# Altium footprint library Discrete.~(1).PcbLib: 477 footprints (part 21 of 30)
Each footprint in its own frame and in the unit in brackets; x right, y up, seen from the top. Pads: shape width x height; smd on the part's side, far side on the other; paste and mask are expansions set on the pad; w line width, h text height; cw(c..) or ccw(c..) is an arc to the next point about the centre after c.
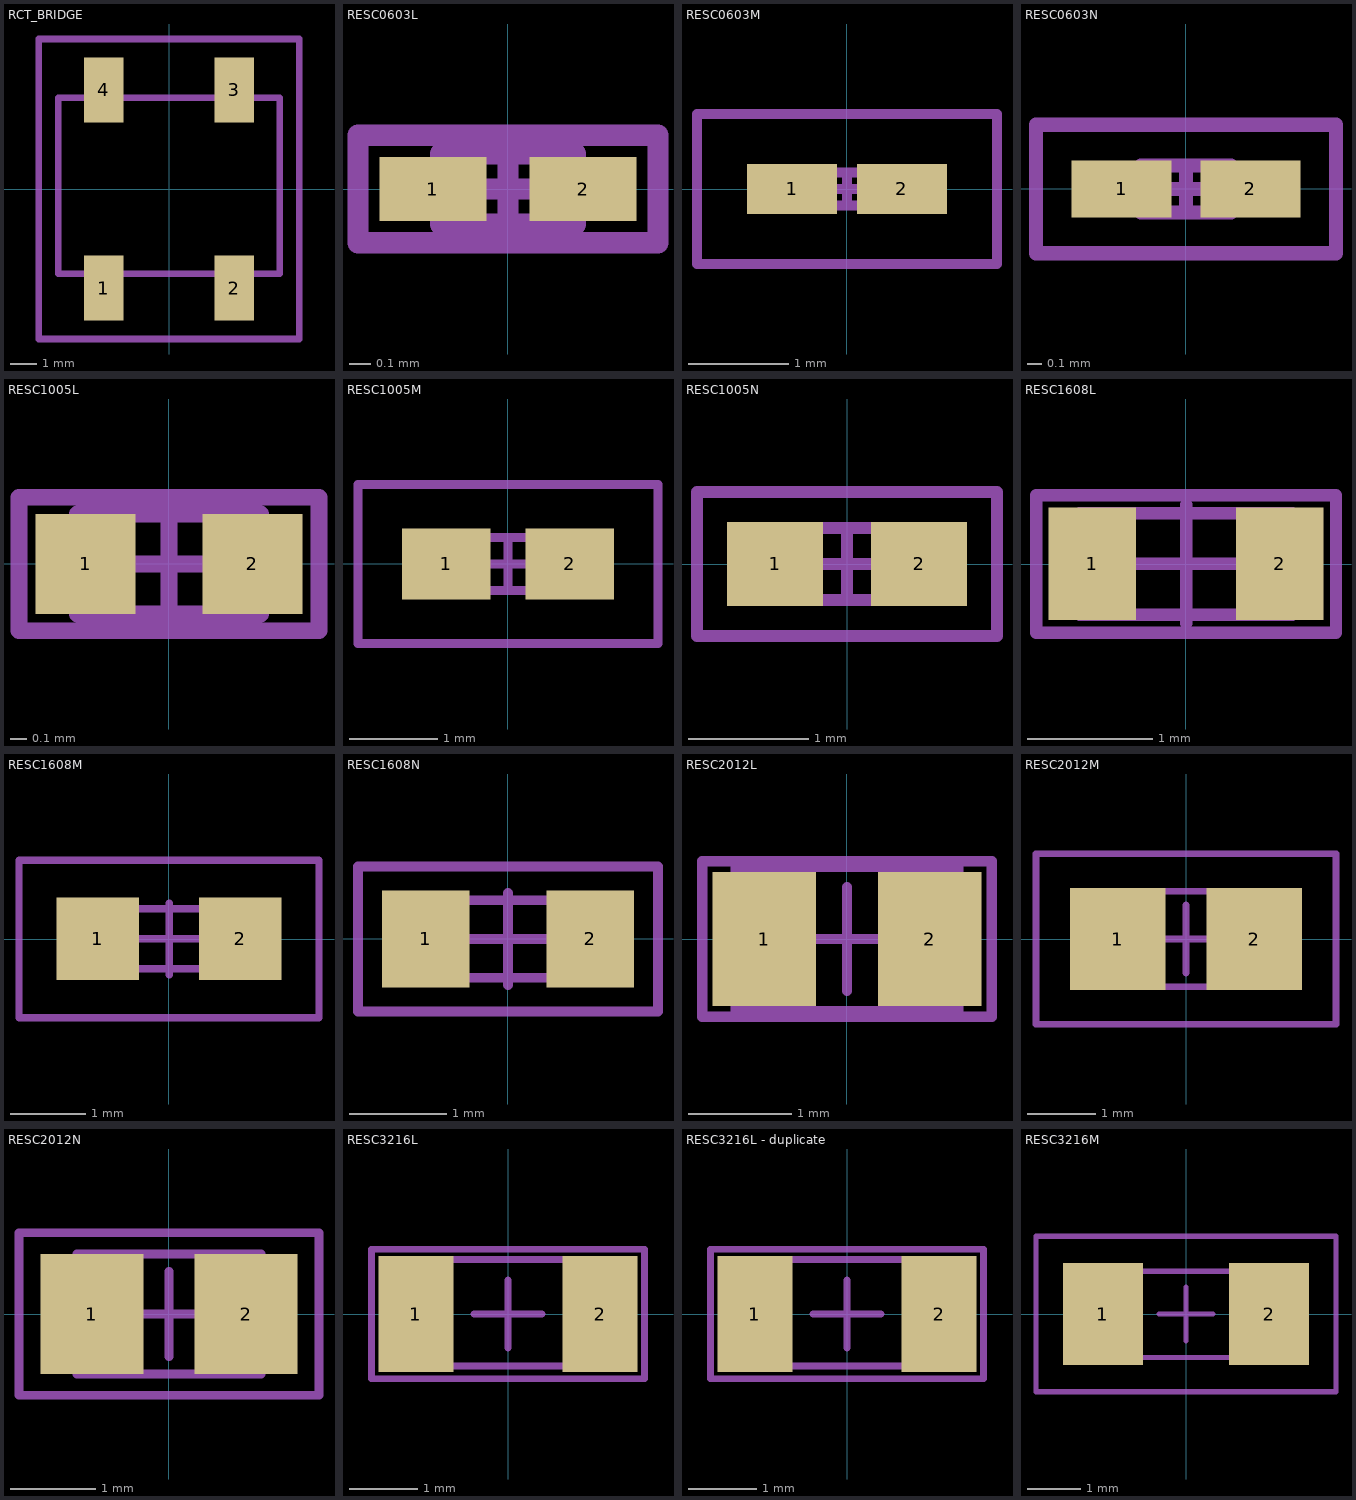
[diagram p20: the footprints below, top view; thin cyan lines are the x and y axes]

## RCT_BRIDGE [mm]
pads (4):
  rect 1.5x2.5 smd: 1(-2.5,-3.8) 2(2.5,-3.8) 3(2.5,3.8) 4(-2.5,3.8)
Mechanical 13:
  lines w0.254: -4.25,-3.25 -4.25,3.5 4.25,3.5 4.25,-3.25 -4.25,-3.25
Mechanical 15:
  lines w0.254: -5,-5.75 -5,5.75 5,5.75 5,-5.75 -5,-5.75
3D body: height 3, standoff 1, extent -4.25,-3.25 4.25,3.5

## RESC0603L [mm] "Chip Resistor, Body 0.6x0.3mm, IPC High Density"
height 0.3
pads (2):
  rect 0.5x0.3 smd: 1(-0.35,0) 2(0.35,0)
Mechanical 13:
  lines w0.1: -0.315,-0.165 0.315,-0.165 0.315,0.165 -0.315,0.165 -0.315,-0.165
Mechanical 15:
  lines w0.1: -0.165,0 0.165,0 ; 0,-0.165 0,0.165 ; -0.7,-0.25 0.7,-0.25 0.7,0.25 -0.7,0.25 -0.7,-0.25
3D body: height 0.3, standoff 0, extent -0.315,-0.165 0.315,0.165

## RESC0603M [mm] "Chip Resistor, Body 0.6x0.3mm, IPC Low Density"
height 0.3
pads (2):
  rect 0.9x0.5 smd: 1(-0.55,0) 2(0.55,0)
Mechanical 13:
  lines w0.1: -0.315,-0.165 -0.315,0.165 0.315,0.165 0.315,-0.165 -0.315,-0.165
Mechanical 15:
  lines w0.1: -0.165,0 0.165,0 ; 0,-0.165 0,0.165 ; -1.5,-0.75 -1.5,0.75 1.5,0.75 1.5,-0.75 -1.5,-0.75
3D body: height 0.3, standoff 0, extent -0.315,-0.165 0.315,0.165

## RESC0603N [mm] "Chip Resistor, Body 0.6x0.3mm, IPC Medium Density"
height 0.3
pads (2):
  rect 0.7x0.4 smd: 1(-0.45,0) 2(0.45,0)
Mechanical 13:
  lines w0.1: -0.315,-0.165 -0.315,0.165 0.315,0.165 0.315,-0.165 -0.315,-0.165
Mechanical 15:
  lines w0.1: -0.165,0 0.165,0 ; 0,-0.165 0,0.165 ; -1.05,-0.45 -1.05,0.45 1.05,0.45 1.05,-0.45 -1.05,-0.45
3D body: height 0.3, standoff 0, extent -0.315,-0.165 0.315,0.165

## RESC1005L [mm] "Chip Resistor, Body 1.1x0.5mm, IPC High Density"
height 0.4
pads (2):
  rect 0.6x0.6 smd: 1(-0.5,0) 2(0.5,0)
Mechanical 13:
  lines w0.1: -0.55,-0.3 -0.55,0.3 0.55,0.3 0.55,-0.3 -0.55,-0.3
Mechanical 15:
  lines w0.1: -0.3,0 0.3,0 ; 0,-0.3 0,0.3 ; -0.9,-0.4 -0.9,0.4 0.9,0.4 0.9,-0.4 -0.9,-0.4
3D body "R 0402.STEP": height 0.3, standoff 0, extent -0.5,-0.25 0.5,0.25

## RESC1005M [mm] "Chip Resistor, Body 1.1x0.5mm, IPC Low Density"
height 0.4
pads (2):
  rect 1x0.8 smd: 1(-0.7,0) 2(0.7,0)
Mechanical 13:
  lines w0.1: -0.55,-0.3 0.55,-0.3 0.55,0.3 -0.55,0.3 -0.55,-0.3
Mechanical 15:
  lines w0.1: -0.3,0 0.3,0 ; 0,-0.3 0,0.3 ; -1.7,-0.9 1.7,-0.9 1.7,0.9 -1.7,0.9 -1.7,-0.9
3D body "R 0402.STEP": height 0.3, standoff 0, extent -0.5,-0.25 0.5,0.25

## RESC1005N [mm] "Chip Resistor, Body 1.1x0.5mm, IPC Medium Density"
height 0.4
pads (2):
  rect 0.8x0.7 smd: 1(-0.6,0) 2(0.6,0)
Mechanical 13:
  lines w0.1: -0.55,-0.3 0.55,-0.3 0.55,0.3 -0.55,0.3 -0.55,-0.3
Mechanical 15:
  lines w0.1: -0.3,0 0.3,0 ; 0,-0.3 0,0.3 ; -1.25,-0.6 1.25,-0.6 1.25,0.6 -1.25,0.6 -1.25,-0.6
3D body "R 0402.STEP": height 0.3, standoff 0, extent -0.5,-0.25 0.5,0.25

## RESC1608L [mm] "Chip Resistor, Body 1.6x0.8mm, IPC High Density"
height 0.6
pads (2):
  rect 0.7x0.9 smd: 1(-0.75,0) 2(0.75,0)
Mechanical 13:
  lines w0.1: -0.85,-0.406 -0.85,0.406 0.85,0.406 0.85,-0.406 -0.85,-0.406
Mechanical 15:
  lines w0.1: -0.475,0 0.475,0 ; 0,-0.475 0,0.475 ; -1.2,-0.55 -1.2,0.55 1.2,0.55 1.2,-0.55 -1.2,-0.55
3D body "R 0603.STEP": height 0.4, standoff 0, extent -0.8,-0.4 0.8,0.4

## RESC1608M [mm] "Chip Resistor, Body 1.6x0.8mm, IPC Low Density"
height 0.6
pads (2):
  rect 1.1x1.1 smd: 1(-0.95,0) 2(0.95,0)
Mechanical 13:
  lines w0.1: -0.85,-0.4 -0.85,0.4 0.85,0.4 0.85,-0.4 -0.85,-0.4
Mechanical 15:
  lines w0.1: -0.475,0 0.475,0 ; 0,-0.475 0,0.475 ; -2,-1.05 -2,1.05 2,1.05 2,-1.05 -2,-1.05
3D body "R 0603.STEP": height 0.4, standoff 0, extent -0.8,-0.4 0.8,0.4

## RESC1608N [mm] "Chip Resistor, Body 1.6x0.8mm, IPC Medium Density"
height 0.6
pads (2):
  rect 0.9x1 smd: 1(-0.85,0) 2(0.85,0)
Mechanical 13:
  lines w0.1: -0.85,-0.4 -0.85,0.4 0.85,0.4 0.85,-0.4 -0.85,-0.4
Mechanical 15:
  lines w0.1: -0.475,0 0.475,0 ; 0,-0.475 0,0.475 ; -1.55,-0.75 -1.55,0.75 1.55,0.75 1.55,-0.75 -1.55,-0.75
3D body "R 0603.STEP": height 0.4, standoff 0, extent -0.8,-0.4 0.8,0.4

## RESC2012L [mm] "Chip Resistor, Body 2.0x1.3mm, IPC High Density"
height 0.65
pads (2):
  rect 1x1.3 smd: 1(-0.8,0) 2(0.8,0)
Mechanical 13:
  lines w0.1: -1.075,-0.7 -1.075,0.7 1.075,0.7 1.075,-0.7 -1.075,-0.7
Mechanical 15:
  lines w0.1: -0.5,0 0.5,0 ; 0,-0.5 0,0.5 ; -1.4,-0.75 -1.4,0.75 1.4,0.75 1.4,-0.75 -1.4,-0.75
3D body "R 0805.STEP": height 0.5, standoff -0.01, extent -1,-0.625 1,0.625

## RESC2012M [mm] "Chip Resistor, Body 2.0x1.3mm, IPC Low Density"
height 0.65
pads (2):
  rect 1.4x1.5 smd: 1(-1,0) 2(1,0)
Mechanical 13:
  lines w0.1: -1.075,-0.7 -1.075,0.7 1.075,0.7 1.075,-0.7 -1.075,-0.7
Mechanical 15:
  lines w0.1: -0.5,0 0.5,0 ; 0,-0.5 0,0.5 ; -2.2,-1.25 -2.2,1.25 2.2,1.25 2.2,-1.25 -2.2,-1.25
3D body "R 0805.STEP": height 0.5, standoff -0.01, extent -1,-0.625 1,0.625

## RESC2012N [mm] "Chip Resistor, Body 2.0x1.3mm, IPC Medium Density"
height 0.65
pads (2):
  rect 1.2x1.4 smd: 1(-0.9,0) 2(0.9,0)
Mechanical 13:
  lines w0.1: -1.075,-0.7 1.075,-0.7 1.075,0.7 -1.075,0.7 -1.075,-0.7
Mechanical 15:
  lines w0.1: -0.5,0 0.5,0 ; 0,-0.5 0,0.5 ; -1.75,-0.95 1.75,-0.95 1.75,0.95 -1.75,0.95 -1.75,-0.95
3D body "R 0805.STEP": height 0.5, standoff -0.01, extent -1,-0.625 1,0.625

## RESC3216L [mm] "Chip Resistor, Body 3.2x1.6mm, IPC High Density"
height 0.71
pads (2):
  rect 1.1x1.7 smd: 1(-1.35,0) 2(1.35,0)
Mechanical 13:
  lines w0.1: -1.6,-0.762 1.6,-0.762 1.6,0.8 -1.6,0.8 -1.6,-0.762
Mechanical 15:
  lines w0.1: -0.5,0 0.5,0 ; 0,-0.5 0,0.5 ; -2,-0.95 2,-0.95 2,0.95 -2,0.95 -2,-0.95
3D body "R 1206.STEP": height 0.55, standoff -0.01, extent -1.6,-0.8 1.6,0.8

## RESC3216L - duplicate [mm] "Chip Resistor, Body 3.2x1.6mm, IPC High Density"
height 0.71
pads (2):
  rect 1.1x1.7 smd: 1(-1.35,0) 2(1.35,0)
Mechanical 13:
  lines w0.1: -1.6,-0.762 -1.6,0.8 1.6,0.8 1.6,-0.762 -1.6,-0.762
Mechanical 15:
  lines w0.1: -0.5,0 0.5,0 ; 0,-0.5 0,0.5 ; -2,-0.95 -2,0.95 2,0.95 2,-0.95 -2,-0.95
3D body "R 1206.STEP": height 0.55, standoff -0.01, extent -1.6,-0.8 1.6,0.8

## RESC3216M [mm] "Chip Resistor, Body 3.2x1.6mm, IPC Low Density"
height 0.71
pads (2):
  rect 1.5x1.9 smd: 1(-1.55,0) 2(1.55,0)
Mechanical 13:
  lines w0.1: -1.6,-0.813 1.601,-0.813 1.601,0.799 0.837,0.799 -1.587,0.799 -1.6,0.8 -1.6,-0.813
Mechanical 15:
  lines w0.1: -0.5,0 0.5,0 ; 0,-0.5 0,0.5 ; -2.8,-1.45 2.8,-1.45 2.8,1.45 -2.8,1.45 -2.8,-1.45
3D body "R 1206.STEP": height 0.55, standoff -0.01, extent -1.6,-0.8 1.6,0.8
